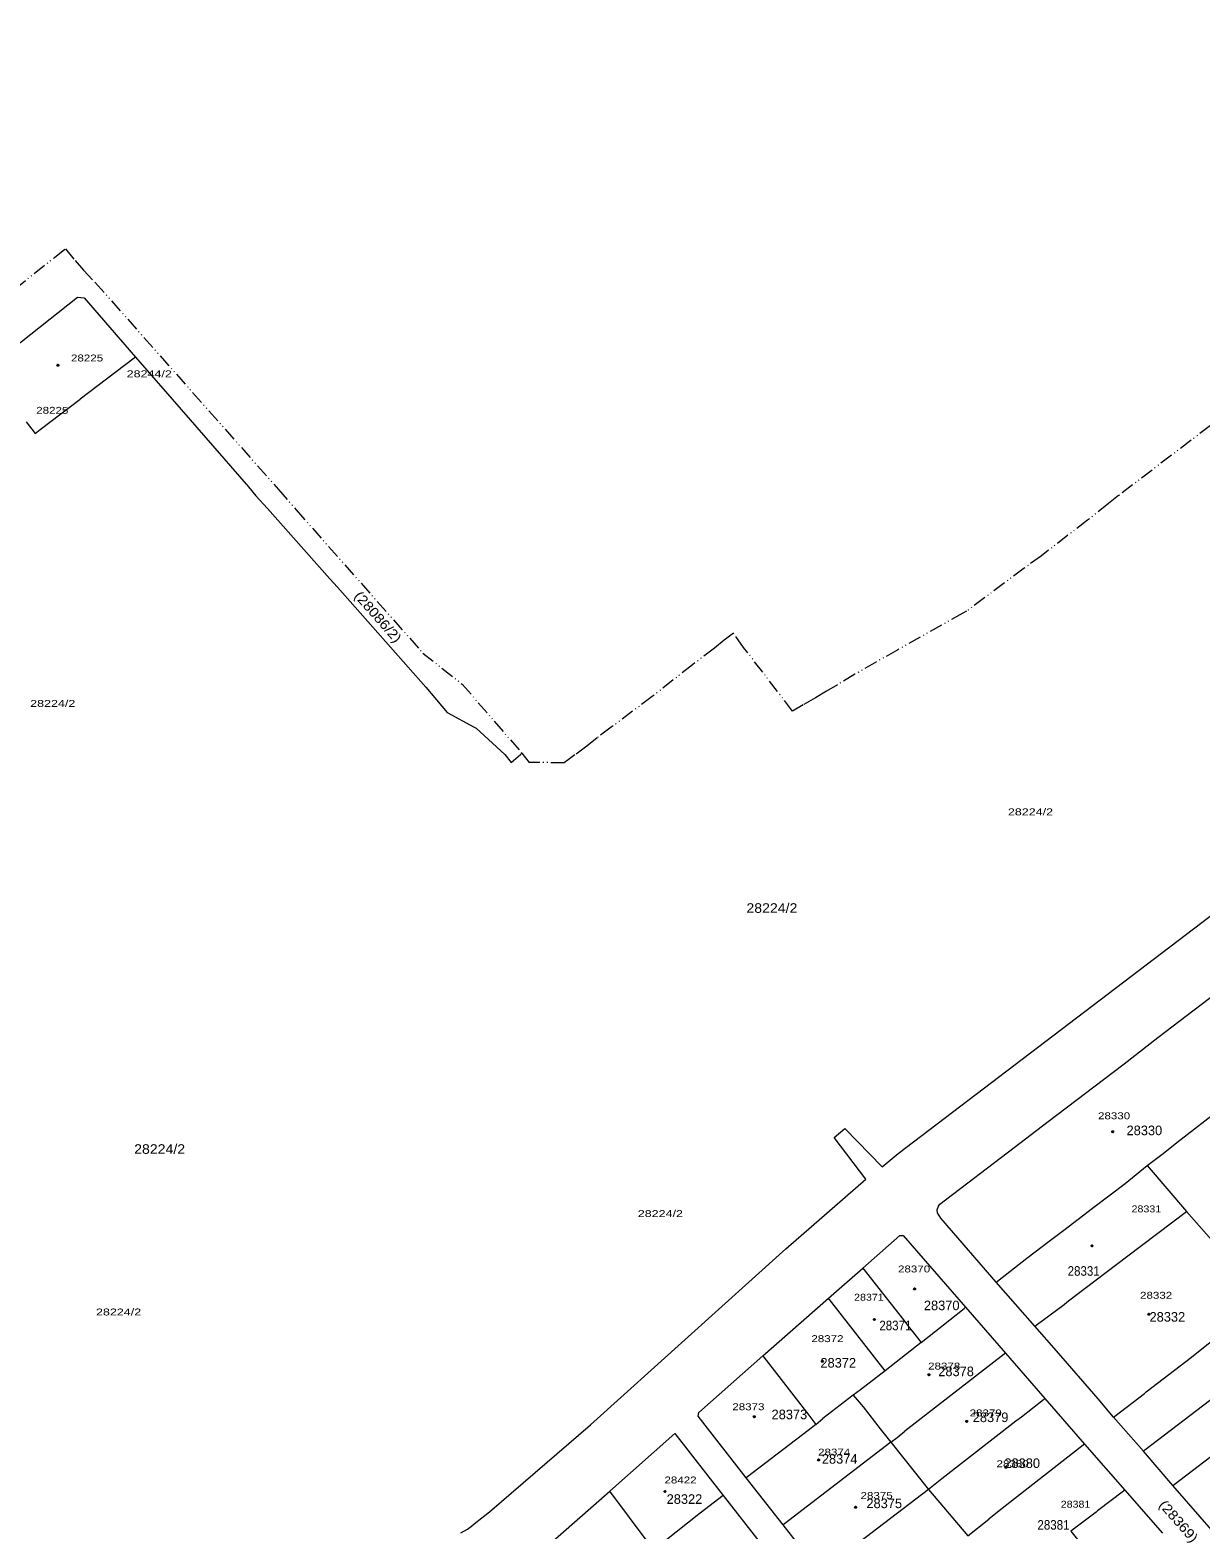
# Model space of a CAD drawing. Extents: x 650553 to 652508, y 239277 to 241647.
# Drawn here: x 651208 to 651648, y 241075 to 241639 of the extents above; entities that cross this region are included whole.
import ezdxf

# ---------------------------------------------------------------- set-up
doc = ezdxf.new("R2010")
doc.units = 0
doc.header["$PDMODE"] = 32
doc.header["$PDSIZE"] = 0.5
doc.linetypes.add('DASH_DOUBLE_DOT', pattern=[9.2, 5, -1.2, 0.3, -1.2, 0.3, -1.2])
for name, color, linetype in [('19', 7, 'Continuous'), ('20', 7, 'Continuous'), ('6', 7, 'Continuous')]:
    doc.layers.add(name, color=color, linetype=linetype)
for name, color, linetype, lineweight in [('2', 7, 'DASH_DOUBLE_DOT', 13), ('3', 7, 'Continuous', 13), ('5', 7, 'Continuous', 13), ('52', 7, 'DASH_DOUBLE_DOT', 13)]:
    doc.layers.add(name, color=color, linetype=linetype, lineweight=lineweight)

msp = doc.modelspace()

# ---------------------------------------------------------------- linework, layer by layer
at = {"layer": '2'}
msp.add_line((651392.957, 241367.009), (651395.726, 241363.548), dxfattribs=at)
msp.add_lwpolyline([(651732.165, 241551.441), (651617.113, 241463.771), (651613.334, 241460.811), (651605.429, 241454.476), (651588.125, 241441.185), (651581.686, 241436.465), (651559.966, 241420.339), (651558.684, 241419.658), (651534.163, 241405.868), (651518.036, 241396.653), (651511.483, 241392.742), (651507.414, 241390.368), (651503.247, 241387.815), (651498.65, 241385.178), (651494.657, 241382.831), (651476.279, 241406.758), (651472.418, 241412.043), (651468.987, 241409.476), (651465.283, 241406.449), (651457.068, 241400.255), (651441.922, 241388.293), (651426.542, 241376.733), (651421.231, 241372.792), (651417.327, 241369.685), (651412.842, 241366.341), (651408.859, 241363.385), (651395.726, 241363.548)], dxfattribs=at)
at = {"layer": '3'}
for points in [[(651370, 241074.13), (651372.52, 241075.56), (651374.02, 241076.72), (651375, 241077.5), (651380.8, 241082.08), (651418.74, 241114.72), (651492.17, 241180.79), (651501.81, 241189.21), (651522.184, 241207.047), (651510.315, 241222.672), (651514.337, 241226.015), (651528.272, 241211.629), (651534.34, 241216.71), (651934.25, 241520.81), (651935.39, 241521.93), (651935.77, 241523.21), (651935.63, 241524.91), (651933.75, 241527.93), (651922.73, 241541.47), (651923.22, 241541.86), (651888.26, 241586.69), (651887.65, 241586.26), (651848.117, 241638.653)], [(651190.84, 241510.5), (651225.94, 241538.26), (651228.47, 241538.01), (651247.73, 241515.82)], [(651247.73, 241515.82), (651261.54, 241500), (651290.27, 241467.08), (651293.03, 241463.73), (651297.33, 241458.97), (651320.78, 241432.45), (651323.63, 241429.43), (651356.91, 241391.76), (651364.9, 241382.35), (651375, 241376.8), (651375.83, 241376.35), (651386.51, 241366.47), (651388.96, 241363.46), (651392.457, 241366.565), (651392.957, 241367.009)], [(651549.43, 241196.89), (651549.98, 241197.62), (651577.87, 241218.95), (651590.72, 241228.7), (651618.7, 241250), (651619.2, 241250.38), (651631.84, 241260.23), (651659.24, 241280.95), (651659.91, 241281.2), (651660.75, 241281.3), (651661.58, 241281.14), (651662.48, 241280.84), (651662.88, 241280.5), (651663.32, 241280.19), (651664.13, 241279.05), (651670.21, 241272.23), (651669.84, 241271.78), (651684.06, 241255.72)], [(651571.12, 241168.34), (651550.4, 241192.42), (651549.15, 241194.37), (651548.92, 241195.46), (651549.43, 241196.89)], [(651521.1, 241173.57), (651534.93, 241185.86), (651536.21, 241185.9), (651559.68, 241158.88), (651574.64, 241141.61), (651589.38, 241124.56), (651604.36, 241107.45), (651619.46, 241090.15), (651633.6, 241074.05)], [(651477.24, 241094.86), (651459.21, 241117.97), (651459.48, 241119.38), (651483.51, 241140.67), (651508.1, 241162.37), (651521.1, 241173.57)], [(651615.22, 241117.65), (651609.5, 241124.48), (651593.77, 241142.49), (651585.63, 241151.78), (651571.12, 241168.34)], [(651683.02, 241080.71), (651661.58, 241064.36), (651658.09, 241068.4), (651637.53, 241091.91), (651626.47, 241104.9), (651615.22, 241117.65)], [(651425.97, 241089.77), (651450.48, 241111.43), (651468.64, 241088.17), (651482.45, 241070.35), (651496.33, 241052.57), (651510.47, 241034.36), (651524.41, 241016.3)], [(651519.26, 241040.99), (651515.47, 241046.09), (651508.81, 241054.48), (651505.02, 241059.33), (651491.06, 241077.17), (651477.24, 241094.86)], [(651391.8, 241028.75), (651377.07, 241046.59), (651401.51, 241068.33), (651425.97, 241089.77)]]:
    msp.add_lwpolyline(points, dxfattribs=at)
at = {"layer": '5'}
for p, q in [((651211.96, 241488.57), (651226.96, 241500)), ((651543, 241145.63), (651529.45, 241135.02)), ((651503.43, 241114.86), (651500.51, 241112.58)), ((651531.59, 241108.23), (651545.7, 241090.47))]:
    msp.add_line(p, q, dxfattribs=at)
for points in [[(651247.73, 241515.82), (651247.23, 241515.439), (651226.96, 241500)], [(651206.68, 241491.44), (651210.12, 241487.14), (651211.96, 241488.57)], [(651627.9, 241212.17), (651633.91, 241216.69), (651639.01, 241220.73), (651656.16, 241234.02), (651662.35, 241238.63), (651671.78, 241246.2), (651676.69, 241250)], [(651571.12, 241168.34), (651571.62, 241168.731), (651582.69, 241177.38), (651591.03, 241183.75), (651596.55, 241187.88), (651607.34, 241196.12), (651613.92, 241201.13), (651619.57, 241205.41), (651627.9, 241212.17), (651642.7, 241194.85)], [(651585.63, 241151.78), (651586.13, 241152.148), (651596.73, 241159.96), (651597.72, 241160.75), (651600.47, 241162.97), (651620.63, 241178.18), (651642.7, 241194.85), (651672.75, 241160.85)], [(651521.1, 241173.57), (651536.38, 241154.19), (651538.62, 241151.22), (651539.16, 241150.45), (651543, 241145.63)], [(651529.45, 241135.02), (651508.49, 241161.87), (651508.1, 241162.37)], [(651543, 241145.63), (651559.18, 241158.483), (651559.68, 241158.88)], [(651615.22, 241117.65), (651615.72, 241118.03), (651626.92, 241126.55), (651627.52, 241127.07), (651644.56, 241140.09), (651650.3, 241144.75), (651666.32, 241157.04)], [(651483.51, 241140.67), (651483.897, 241140.17), (651500.76, 241118.37), (651501.11, 241117.86)], [(651574.64, 241141.61), (651574.14, 241141.223), (651536.8, 241112.3)], [(651529.45, 241135.02), (651520.13, 241127.93), (651517.46, 241125.92), (651506.07, 241117.08)], [(651626.47, 241104.9), (651626.97, 241105.282), (651661.32, 241131.53)], [(651517.46, 241125.92), (651521.22, 241121.43), (651527.51, 241113.21), (651531.59, 241108.23), (651533.99, 241110.03), (651536.8, 241112.3)], [(651589.38, 241124.56), (651588.88, 241124.159), (651580.7, 241117.59), (651578.54, 241116.06), (651550.77, 241094.48), (651545.7, 241090.47), (651560.44, 241073), (651568.43, 241079.26)], [(651501.11, 241117.86), (651503.43, 241114.86), (651506.07, 241117.08)], [(651500.51, 241112.58), (651477.74, 241095.241), (651477.24, 241094.86)], [(651531.59, 241108.23), (651491.56, 241077.553), (651491.06, 241077.17)], [(651604.36, 241107.45), (651603.86, 241107.059), (651572.33, 241082.38), (651568.43, 241079.26)], [(651637.53, 241091.91), (651638.03, 241092.294), (651660.76, 241109.74), (651662.21, 241107.67)], [(651447.23, 241071.56), (651442.48, 241067.94), (651440.75, 241070.06), (651425.97, 241089.77)], [(651545.7, 241090.47), (651505.52, 241059.713), (651505.02, 241059.33)], [(651619.46, 241090.15), (651618.96, 241089.772), (651609.27, 241082.45), (651608.66, 241081.92), (651599.23, 241074.74), (651613.57, 241056.87)], [(651468.64, 241088.17), (651468.14, 241087.788), (651458.84, 241080.69), (651447.23, 241071.56)]]:
    msp.add_lwpolyline(points, dxfattribs=at)
at = {"layer": '52'}
msp.add_lwpolyline([(651094.598, 241455.508), (651209.715, 241547.174), (651217.351, 241553.182), (651221.481, 241556.469), (651225.125, 241552.069), (651228.25, 241548.445), (651232.659, 241543.778), (651301.499, 241466.063), (651308.16, 241458.417), (651355.707, 241404.632), (651370.57, 241392.914), (651392.957, 241367.009)], dxfattribs=at)
at = {"layer": '6'}
for p in [(651218.628, 241512.7), (651614.947, 241224.82), (651607.18, 241181.975), (651540.477, 241165.765), (651525.35, 241154.295), (651628.493, 241156.25), (651505.872, 241138.615), (651545.882, 241133.555), (651480.277, 241117.765), (651560.071, 241116.04), (651504.443, 241101.545), (651574.793, 241098.78), (651446.745, 241089.685), (651518.323, 241083.78)]:
    msp.add_point(p, dxfattribs=at)

# ---------------------------------------------------------------- texts
at = {"layer": '19', "width": 1.15}
for s, rotation, p in [('(28086/2)', 311.459, (651329.698, 241425.913)), ('(28369)', 311.292, (651632.029, 241084.512))]:
    msp.add_text(s, height=3.6, rotation=rotation, dxfattribs=at).set_placement(p)
at = {"layer": '19'}
for s, width, p in [('28224/2', 1.1, (651477.311, 241307.047)), ('28224/2', 1.1, (651247.286, 241216.524)), ('28331', 0.9, (651597.993, 241170.724)), ('28371', 0.9, (651527.258, 241150.248)), ('28381', 0.9, (651586.654, 241075.351))]:
    msp.add_text(s, height=3.6, dxfattribs=dict(at, width=width)).set_placement(p)
for s, p in [('28330', (651620.13, 241223.528)), ('28370', (651543.996, 241157.792)), ('28332', (651628.77, 241153.481)), ('28372', (651505.12, 241136.239)), ('28378', (651549.397, 241133.006)), ('28373', (651486.761, 241116.841)), ('28379', (651562.356, 241115.763)), ('28374', (651505.659, 241100.137)), ('28380', (651574.234, 241098.521)), ('28322', (651447.342, 241085.05)), ('28375', (651522.398, 241083.434))]:
    msp.add_text(s, height=3.6, dxfattribs=at).set_placement(p)
at = {"layer": '20'}
for s, width, p in [('28225', 1.25, (651223.55, 241514.152)), ('28244/2', 1.35, (651244.474, 241508.2)), ('28225', 1.25, (651210.491, 241494.496)), ('28224/2', 1.35, (651208.217, 241384.406)), ('28224/2', 1.35, (651575.552, 241343.666)), ('28330', 1.25, (651609.405, 241229.514)), ('28331', 1.15, (651622.019, 241194.536)), ('28224/2', 1.35, (651436.501, 241192.774)), ('28370', 1.25, (651534.265, 241171.972)), ('28371', 1.15, (651517.776, 241161.359)), ('28332', 1.25, (651625.199, 241162.086)), ('28224/2', 1.35, (651232.949, 241155.815)), ('28372', 1.25, (651501.711, 241145.797)), ('28378', 1.25, (651545.568, 241135.503)), ('28373', 1.25, (651472.01, 241120.229)), ('28379', 1.25, (651561.173, 241117.895)), ('28374', 1.25, (651504.243, 241103.183)), ('28380', 1.25, (651571.276, 241098.808)), ('28422', 1.25, (651446.514, 241092.712)), ('28375', 1.25, (651520.196, 241086.895)), ('28381', 1.15, (651595.409, 241083.611))]:
    msp.add_text(s, height=2.6, dxfattribs=dict(at, width=width)).set_placement(p)

doc.saveas('drawing.dxf')
